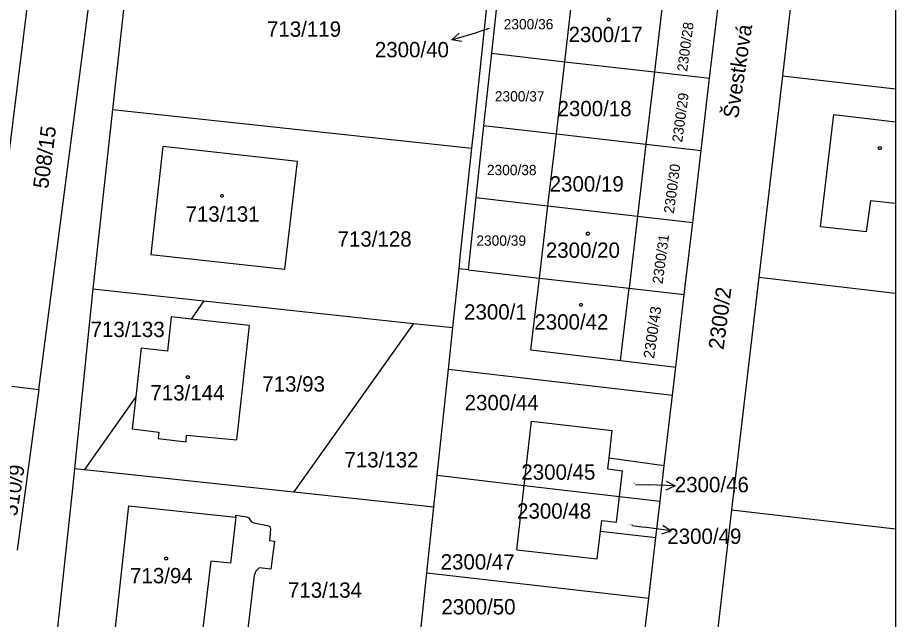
# Model space of a CAD drawing. Extents: x -639590 to -639298, y -1193269 to -1192863.
# Drawn here: x -639395.8 to -639298.4, y -1193011.1 to -1192944.4 of the extents above; entities that cross this region are included whole.
import ezdxf

# ---------------------------------------------------------------- set-up
doc = ezdxf.new("R2010")
doc.units = 0
for name, color, linetype in [('Vrstva 1', 7, 'Continuous'), ('Vrstva 2', 7, 'Continuous'), ('Vrstva 4', 7, 'Continuous'), ('Vrstva 5', 7, 'Continuous'), ('Vrstva 61', 7, 'Continuous'), ('Vrstva 7', 7, 'Continuous')]:
    doc.layers.add(name, color=color, linetype=linetype)

msp = doc.modelspace()

# ---------------------------------------------------------------- linework, layer by layer
at = {"layer": 'Vrstva 1'}
for p, q in [((-639383.03, -1192934.71), (-639385.21, -1192954.59)), ((-639393.89, -1192936.45), (-639396.82, -1192960.36)), ((-639393.41, -1192985.63), (-639387.1, -1192937.37)), ((-639345.16, -1192956.92), (-639343.26, -1192938.99)), ((-639309.56, -1192939.2), (-639310.92, -1192950.83)), ((-639342.35, -1192940.34), (-639343.21, -1192948.35)), ((-639335.07, -1192949.28), (-639334.13, -1192941.29)), ((-639324.19, -1192942.43), (-639325.13, -1192950.42)), ((-639319.01, -1192951.12), (-639318.07, -1192943.13)), ((-639343.21, -1192948.35), (-639344.07, -1192956.35)), ((-639343.21, -1192948.35), (-639335.07, -1192949.28)), ((-639336, -1192957.28), (-639335.07, -1192949.28)), ((-639335.07, -1192949.28), (-639325.13, -1192950.42)), ((-639325.13, -1192950.42), (-639326.07, -1192958.42)), ((-639325.13, -1192950.42), (-639319.01, -1192951.12)), ((-639310.92, -1192950.83), (-639313.54, -1192973.18)), ((-639310.92, -1192950.83), (-639298.391, -1192952.297)), ((-639319.94, -1192959.12), (-639319.01, -1192951.12)), ((-639385.21, -1192954.59), (-639387.39, -1192974.48)), ((-639385.21, -1192954.59), (-639345.37, -1192958.88)), ((-639306.71, -1192967.58), (-639305.24, -1192955.15)), ((-639305.24, -1192955.15), (-639298.391, -1192955.938)), ((-639344.07, -1192956.35), (-639344.93, -1192964.35)), ((-639344.07, -1192956.35), (-639336, -1192957.28)), ((-639345.37, -1192958.88), (-639345.16, -1192956.92)), ((-639336.94, -1192965.27), (-639336, -1192957.28)), ((-639336, -1192957.28), (-639326.07, -1192958.42)), ((-639379.65, -1192958.7), (-639380.96, -1192970.68)), ((-639364.71, -1192960.36), (-639379.65, -1192958.7)), ((-639326.07, -1192958.42), (-639327, -1192966.41)), ((-639326.07, -1192958.42), (-639319.94, -1192959.12)), ((-639346.65, -1192970.97), (-639345.37, -1192958.88)), ((-639320.88, -1192967.11), (-639319.94, -1192959.12)), ((-639366.1, -1192972.28), (-639364.71, -1192960.36)), ((-639344.93, -1192964.35), (-639345.79, -1192972.36)), ((-639344.93, -1192964.35), (-639336.94, -1192965.27)), ((-639337.88, -1192973.27), (-639336.94, -1192965.27)), ((-639336.94, -1192965.27), (-639327, -1192966.41)), ((-639301.16, -1192964.71), (-639301.64, -1192968.16)), ((-639298.391, -1192965.018), (-639301.16, -1192964.71)), ((-639327, -1192966.41), (-639327.94, -1192974.41)), ((-639327, -1192966.41), (-639320.88, -1192967.11)), ((-639321.82, -1192975.11), (-639320.88, -1192967.11)), ((-639301.64, -1192968.16), (-639306.71, -1192967.58)), ((-639380.96, -1192970.68), (-639366.1, -1192972.28)), ((-639346.79, -1192972.24), (-639346.65, -1192970.97)), ((-639347.48, -1192978.77), (-639346.79, -1192972.24)), ((-639345.79, -1192972.36), (-639346.79, -1192972.24)), ((-639345.79, -1192972.36), (-639337.88, -1192973.27)), ((-639338.82, -1192981.25), (-639337.88, -1192973.27)), ((-639337.88, -1192973.27), (-639327.94, -1192974.41)), ((-639313.54, -1192973.18), (-639316.56, -1192998.97)), ((-639313.54, -1192973.18), (-639298.391, -1192974.948)), ((-639328.88, -1192982.42), (-639327.94, -1192974.41)), ((-639327.94, -1192974.41), (-639321.82, -1192975.11)), ((-639387.39, -1192974.48), (-639389.43, -1192994.38)), ((-639387.39, -1192974.48), (-639375.09, -1192975.8)), ((-639322.76, -1192983.14), (-639321.82, -1192975.11)), ((-639375.09, -1192975.8), (-639376.52, -1192977.82)), ((-639375.09, -1192975.8), (-639351.85, -1192978.3)), ((-639378.73, -1192977.57), (-639379.13, -1192981.37)), ((-639376.52, -1192977.82), (-639378.73, -1192977.57)), ((-639370.03, -1192978.54), (-639376.52, -1192977.82)), ((-639351.85, -1192978.3), (-639365.1, -1192996.99)), ((-639351.85, -1192978.3), (-639347.48, -1192978.77)), ((-639371.45, -1192991.2), (-639370.03, -1192978.54)), ((-639347.97, -1192983.38), (-639347.48, -1192978.77)), ((-639382.05, -1192981.06), (-639382.64, -1192986.44)), ((-639379.13, -1192981.37), (-639382.05, -1192981.06)), ((-639338.82, -1192981.25), (-639328.88, -1192982.42)), ((-639328.88, -1192982.42), (-639322.76, -1192983.14)), ((-639323.13, -1192986.27), (-639322.76, -1192983.14)), ((-639349.21, -1192995.14), (-639347.97, -1192983.38)), ((-639347.97, -1192983.38), (-639323.13, -1192986.27)), ((-639396.4, -1192985.25), (-639393.41, -1192985.63)), ((-639393.41, -1192985.63), (-639395.79, -1193003.46)), ((-639382.64, -1192986.44), (-639388.35, -1192994.49)), ((-639382.64, -1192986.44), (-639383.03, -1192990.01)), ((-639324.04, -1192994.08), (-639323.13, -1192986.27)), ((-639383.03, -1192990.01), (-639380.1, -1192990.35)), ((-639339.57, -1192996.27), (-639338.74, -1192989.14)), ((-639338.74, -1192989.14), (-639329.8, -1192990.18)), ((-639380.1, -1192990.35), (-639380.16, -1192991.08)), ((-639377.07, -1192991.44), (-639377.01, -1192990.69)), ((-639377.01, -1192990.69), (-639371.45, -1192991.2)), ((-639330.15, -1192993.23), (-639329.8, -1192990.18)), ((-639380.16, -1192991.08), (-639377.07, -1192991.44)), ((-639330.29, -1192994.42), (-639330.15, -1192993.23)), ((-639330.15, -1192993.23), (-639324.04, -1192994.08)), ((-639389.43, -1192994.38), (-639389.63, -1192996.3)), ((-639389.43, -1192994.38), (-639388.35, -1192994.49)), ((-639388.35, -1192994.49), (-639365.1, -1192996.99)), ((-639330.29, -1192994.42), (-639328.66, -1192994.65)), ((-639328.99, -1192997.5), (-639328.66, -1192994.65)), ((-639324.5, -1192998.02), (-639324.04, -1192994.08)), ((-639349.58, -1192998.66), (-639349.21, -1192995.14)), ((-639349.21, -1192995.14), (-639339.57, -1192996.27)), ((-639389.63, -1192996.3), (-639391.56, -1193014.27)), ((-639340.4, -1193003.4), (-639339.57, -1192996.27)), ((-639339.57, -1192996.27), (-639328.99, -1192997.5)), ((-639365.1, -1192996.99), (-639349.58, -1192998.66)), ((-639329.33, -1193000.35), (-639328.99, -1192997.5)), ((-639328.99, -1192997.5), (-639324.5, -1192998.02)), ((-639385, -1193013.06), (-639383.4, -1192998.52)), ((-639383.4, -1192998.52), (-639371.56, -1192999.81)), ((-639350.36, -1193005.95), (-639349.58, -1192998.66)), ((-639324.98, -1193002.06), (-639324.5, -1192998.02)), ((-639371.56, -1192999.81), (-639371.54, -1192999.58)), ((-639371.54, -1192999.58), (-639370.37, -1192999.75)), ((-639316.56, -1192998.97), (-639319.4, -1193023.24)), ((-639316.56, -1192998.97), (-639298.391, -1193001.096)), ((-639370.37, -1192999.75), (-639370.12, -1192999.88)), ((-639370.12, -1192999.88), (-639369.99, -1193000.06)), ((-639369.99, -1193000.06), (-639369.86, -1193000.28)), ((-639369.86, -1193000.28), (-639369.57, -1193000.43)), ((-639369.57, -1193000.43), (-639368.03, -1193000.71)), ((-639368.03, -1193000.71), (-639367.76, -1193000.83)), ((-639331.1, -1193001.35), (-639330.97, -1193000.16)), ((-639330.97, -1193000.16), (-639329.33, -1193000.35)), ((-639367.71, -1193001.13), (-639367.82, -1193002.4)), ((-639367.76, -1193000.83), (-639367.71, -1193001.13)), ((-639331.46, -1193004.43), (-639331.1, -1193001.35)), ((-639331.1, -1193001.35), (-639324.98, -1193002.06)), ((-639367.82, -1193002.4), (-639367.25, -1193002.47)), ((-639367.25, -1193002.47), (-639367.65, -1193005.55)), ((-639325.76, -1193008.79), (-639324.98, -1193002.06)), ((-639340.4, -1193003.4), (-639331.46, -1193004.43)), ((-639368.97, -1193005.42), (-639369.34, -1193005.78)), ((-639367.65, -1193005.55), (-639368.97, -1193005.42)), ((-639369.53, -1193006.28), (-639370.56, -1193015.2)), ((-639369.34, -1193005.78), (-639369.53, -1193006.28)), ((-639351.45, -1193016.27), (-639350.36, -1193005.95)), ((-639350.36, -1193005.95), (-639325.76, -1193008.79)), ((-639326.66, -1193016.49), (-639325.76, -1193008.79))]:
    msp.add_line(p, q, dxfattribs=at)
at = {"layer": 'Vrstva 4'}
for p, q in [((-639371.56, -1192999.81), (-639372.13, -1193004.88)), ((-639374.33, -1193004.66), (-639375.43, -1193014.08)), ((-639372.13, -1193004.88), (-639374.33, -1193004.66))]:
    msp.add_line(p, q, dxfattribs=at)
at = {"layer": 'Vrstva 5'}
for points in [[(-639330.11, -1192944.46), (-639330.02, -1192944.61), (-639330.11, -1192944.76), (-639330.29, -1192944.76), (-639330.38, -1192944.61), (-639330.29, -1192944.46)], [(-639300.03, -1192958.72), (-639299.94, -1192958.87), (-639300.03, -1192959.02), (-639300.21, -1192959.02), (-639300.3, -1192958.87), (-639300.21, -1192958.72)], [(-639372.99, -1192963.99), (-639372.9, -1192964.14), (-639372.99, -1192964.29), (-639373.17, -1192964.29), (-639373.26, -1192964.14), (-639373.17, -1192963.99)], [(-639332.41, -1192968.2), (-639332.32, -1192968.35), (-639332.41, -1192968.5), (-639332.59, -1192968.5), (-639332.68, -1192968.35), (-639332.59, -1192968.2)], [(-639333.18, -1192976.11), (-639333.09, -1192976.26), (-639333.18, -1192976.41), (-639333.36, -1192976.41), (-639333.45, -1192976.26), (-639333.36, -1192976.11)], [(-639376.77, -1192984.13), (-639376.68, -1192984.28), (-639376.77, -1192984.43), (-639376.95, -1192984.43), (-639377.04, -1192984.28), (-639376.95, -1192984.13)], [(-639379.19, -1193004.22), (-639379.1, -1193004.37), (-639379.19, -1193004.52), (-639379.37, -1193004.52), (-639379.46, -1193004.37), (-639379.37, -1193004.22)]]:
    msp.add_lwpolyline(points, close=True, dxfattribs=at)
at = {"layer": 'Vrstva 61'}
msp.add_lwpolyline([(-639298.391, -1192863.27), (-639298.391, -1193268.77)], dxfattribs=at)
at = {"layer": 'Vrstva 7'}
for p, q in [((-639347.588, -1192946.869), (-639344.72, -1192945.99)), ((-639343.46, -1192945.61), (-639344.72, -1192945.99)), ((-639327.22, -1192996.16), (-639325.82, -1192996.22)), ((-639322.822, -1192996.335), (-639325.82, -1192996.22)), ((-639327.64, -1193000.73), (-639326.25, -1193000.91)), ((-639323.276, -1193001.306), (-639326.25, -1193000.91))]:
    msp.add_line(p, q, dxfattribs=at)
for points in [[(-639346.486, -1192947.054), (-639347.588, -1192946.869), (-639346.779, -1192946.098)], [(-639323.802, -1192995.797), (-639322.822, -1192996.335), (-639323.841, -1192996.796)], [(-639324.201, -1193000.678), (-639323.276, -1193001.306), (-639324.334, -1193001.67)]]:
    msp.add_lwpolyline(points, dxfattribs=at)

# ---------------------------------------------------------------- texts
at = {"layer": 'Vrstva 2'}
for s, height, p in [('713/119', 1.7, (-639368.095, -1192946.51)), ('2300/36', 1.14, (-639341.839, -1192945.69)), ('2300/40', 0.1, (-639343.757, -1192945.61)), ('2300/17', 1.7, (-639334.648, -1192947.11)), ('2300/37', 1.14, (-639342.822, -1192953.69)), ('2300/18', 1.7, (-639335.868, -1192955.33)), ('2300/38', 1.14, (-639343.702, -1192961.86)), ('2300/19', 1.7, (-639336.738, -1192963.68)), ('713/131', 1.7, (-639377.132, -1192967.02)), ('713/128', 1.7, (-639360.266, -1192969.79)), ('2300/39', 1.14, (-639344.869, -1192969.69)), ('2300/20', 1.7, (-639337.166, -1192971.03)), ('2300/1', 1.7, (-639346.233, -1192977.88)), ('2300/42', 1.7, (-639338.44, -1192978.99)), ('713/133', 1.7, (-639387.657, -1192979.82)), ('713/93', 1.7, (-639368.618, -1192985.87)), ('713/144', 1.7, (-639381.023, -1192986.85)), ('2300/44', 1.7, (-639346.173, -1192987.94)), ('713/132', 1.7, (-639359.503, -1192994.28)), ('2300/45', 1.7, (-639339.883, -1192995.64)), ('2300/46', 0.1, (-639327.496, -1192996.08)), ('2300/48', 1.7, (-639340.356, -1192999.96)), ('2300/49', 0.1, (-639327.996, -1193000.65)), ('2300/47', 1.7, (-639348.833, -1193005.6)), ('713/94', 1.7, (-639383.281, -1193007.13)), ('713/134', 1.7, (-639365.77, -1193008.73)), ('2300/50', 1.7, (-639348.743, -1193010.58))]:
    msp.add_text(s, height=height, dxfattribs=at).set_placement(p)
for s, height, rotation, p in [('2300/28', 1.14, 82.33404, (-639321.498, -1192950.423)), ('2300/29', 1.14, 82.33404, (-639322.046, -1192958.279)), ('508/15', 1.7, 82.50592, (-639392.371, -1192963.418)), ('2300/30', 1.14, 82.33404, (-639322.97, -1192966.166)), ('2300/31', 1.14, 82.33404, (-639324.226, -1192973.967)), ('2300/2', 1.7, 82.62051, (-639317.46, -1192981.285)), ('2300/43', 1.2, 81.87567, (-639325.166, -1192982.254)), ('510/9', 1.7, 81.13083, (-639395.827, -1192999.741))]:
    msp.add_text(s, height=height, rotation=rotation, dxfattribs=at).set_placement(p)
at = {"layer": 'Vrstva 7'}
msp.add_text('Švestková', height=1.7, rotation=81.36001, dxfattribs=at).set_placement((-639315.844, -1192955.645))
for s, p in [('2300/40', (-639356.133, -1192948.79)), ('2300/46', (-639322.866, -1192997.03)), ('2300/49', (-639323.696, -1193002.76))]:
    msp.add_text(s, height=1.7, dxfattribs=at).set_placement(p)

doc.saveas('drawing.dxf')
